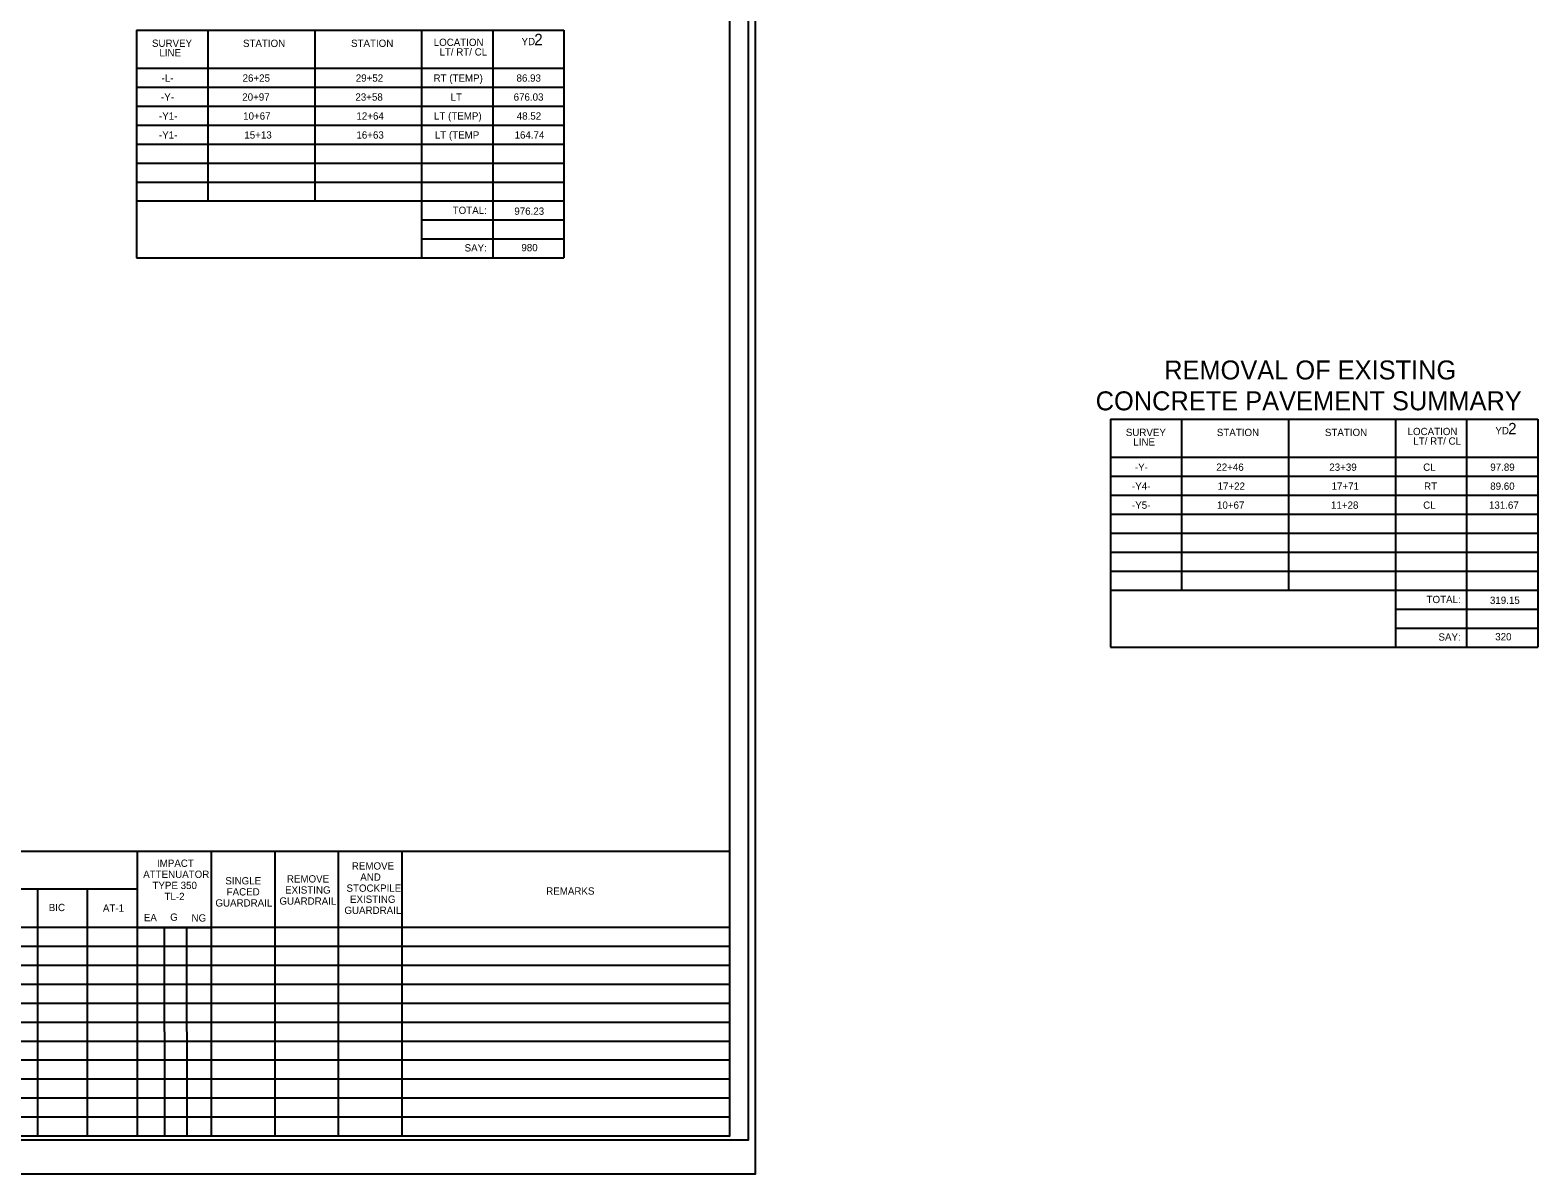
# Model space of a CAD drawing. Extents: x 1729625 to 1732014, y 538843 to 541329.
# Drawn here: x 1731022 to 1732014, y 539915 to 540668 of the extents above; entities that cross this region are included whole.
import ezdxf

# ---------------------------------------------------------------- set-up
doc = ezdxf.new("R2010")
doc.units = 0
for name, color, linetype in [('Prop EOT', 7, 'Continuous'), ('Prop Horizontal Alignment', 7, 'Continuous'), ('Sheet Cutting Line CELL', 7, 'Continuous'), ('Sheet Plot Border Inside CELL', 7, 'Continuous'), ('Sheet Plot Border Outside CELL', 7, 'Continuous'), ('Sheet Summary CELL', 7, 'Continuous')]:
    doc.layers.add(name, color=color, linetype=linetype)

msp = doc.modelspace()

# ---------------------------------------------------------------- linework, layer by layer
at = {"layer": 'Prop EOT'}
for p, q in [((1731092.06, 540668.17), (1731373.41, 540668.17)), ((1731092.06, 540668.17), (1731092.06, 540518.17)), ((1731138.96, 540668.17), (1731138.96, 540555.67)), ((1731209.31, 540668.17), (1731209.31, 540555.67)), ((1731279.61, 540668.17), (1731279.61, 540518.17)), ((1731326.51, 540668.17), (1731326.51, 540518.17)), ((1731373.41, 540668.17), (1731373.41, 540518.17)), ((1731092.06, 540643.17), (1731373.41, 540643.17)), ((1731092.06, 540630.67), (1731373.41, 540630.67)), ((1731092.06, 540618.17), (1731373.41, 540618.17)), ((1731092.06, 540605.67), (1731373.41, 540605.67)), ((1731092.06, 540593.17), (1731373.41, 540593.17)), ((1731092.06, 540580.67), (1731373.41, 540580.67)), ((1731092.06, 540568.17), (1731373.41, 540568.17)), ((1731092.06, 540555.67), (1731373.41, 540555.67)), ((1731279.61, 540543.17), (1731373.41, 540543.17)), ((1731279.61, 540530.67), (1731373.41, 540530.67)), ((1731092.06, 540518.17), (1731373.41, 540518.17)), ((1731733.08, 540411.88), (1732014.43, 540411.88)), ((1731733.08, 540411.88), (1731733.08, 540261.88)), ((1731779.98, 540411.88), (1731779.98, 540299.38)), ((1731850.33, 540411.88), (1731850.33, 540299.38)), ((1731920.63, 540411.88), (1731920.63, 540261.88)), ((1731967.53, 540411.88), (1731967.53, 540261.88)), ((1732014.43, 540411.88), (1732014.43, 540261.88)), ((1731733.08, 540386.88), (1732014.43, 540386.88)), ((1731733.08, 540374.38), (1732014.43, 540374.38)), ((1731733.08, 540361.88), (1732014.43, 540361.88)), ((1731733.08, 540349.38), (1732014.43, 540349.38)), ((1731733.08, 540336.88), (1732014.43, 540336.88)), ((1731733.08, 540324.38), (1732014.43, 540324.38)), ((1731733.08, 540311.88), (1732014.43, 540311.88)), ((1731733.08, 540299.38), (1732014.43, 540299.38)), ((1731920.63, 540286.88), (1732014.43, 540286.88)), ((1731920.63, 540274.38), (1732014.43, 540274.38)), ((1731733.08, 540261.88), (1732014.43, 540261.88)), ((1729982.47, 540127.41), (1731482.47, 540127.41)), ((1731092.42, 540127.41), (1731092.42, 539939.91)), ((1731141.27, 540127.41), (1731141.27, 539939.91)), ((1731183.07, 540127.41), (1731183.07, 539939.91)), ((1731224.87, 540127.41), (1731224.87, 539939.91)), ((1731266.72, 540127.41), (1731266.72, 539939.91)), ((1731092.42, 540102.41), (1730615.27, 540102.41)), ((1731026.82, 540102.41), (1731026.82, 539939.91)), ((1731059.62, 540102.41), (1731059.62, 539939.91)), ((1729982.47, 540077.41), (1731482.47, 540077.41)), ((1731092.42, 540077.16), (1731141.02, 540077.16)), ((1731110.28, 540077.16), (1731110.36, 539939.91)), ((1731125.02, 540077.16), (1731125.1, 539939.91)), ((1729982.47, 540064.91), (1731482.47, 540064.91)), ((1729982.47, 540052.41), (1731482.47, 540052.41)), ((1729982.47, 540039.91), (1731482.47, 540039.91)), ((1729982.47, 540027.41), (1731482.47, 540027.41)), ((1729982.47, 540014.91), (1731482.47, 540014.91)), ((1729982.47, 540002.41), (1731482.47, 540002.41)), ((1729982.47, 540002.41), (1731482.47, 540002.41)), ((1729982.47, 539989.91), (1731482.47, 539989.91)), ((1729982.47, 539977.41), (1731482.47, 539977.41)), ((1729982.47, 539964.91), (1731482.47, 539964.91)), ((1729982.47, 539952.41), (1731482.47, 539952.41))]:
    msp.add_line(p, q, dxfattribs=at)
at = {"layer": 'Prop Horizontal Alignment'}
for p, q in [((1731233.31, 540668.12), (1731233.31, 540668.12)), ((1731239.56, 540668.02), (1731239.56, 540668.02)), ((1731254.21, 540668.12), (1731254.21, 540668.12)), ((1731874.33, 540411.83), (1731874.33, 540411.83)), ((1731880.58, 540411.73), (1731880.58, 540411.73)), ((1731889.63, 540411.93), (1731889.63, 540411.93)), ((1731895.23, 540411.83), (1731895.23, 540411.83))]:
    msp.add_line(p, q, dxfattribs=at)
at = {"layer": 'Sheet Cutting Line CELL'}
msp.add_line((1729815.47, 539914.91), (1731499.47, 539914.91), dxfattribs=at)
at = {"layer": 'Sheet Plot Border Inside CELL'}
msp.add_lwpolyline([(1731494.97, 540992.46), (1729828.47, 540992.46), (1729828.47, 539937.36), (1731494.97, 539937.36)], close=True, dxfattribs=at)
at = {"layer": 'Sheet Plot Border Outside CELL'}
msp.add_lwpolyline([(1731499.47, 541014.91), (1729815.47, 541014.91), (1729815.47, 539914.91), (1731499.47, 539914.91)], close=True, dxfattribs=at)
at = {"layer": 'Sheet Summary CELL'}
msp.add_lwpolyline([(1731482.47, 540989.91), (1729982.47, 540989.91), (1729982.47, 539939.91), (1731482.47, 539939.91)], close=True, dxfattribs=at)

# ---------------------------------------------------------------- texts
at = {"layer": 'Prop EOT'}
for s, height, p in [('YD', 4.8, (1731345.47, 540658.29)), ('2', 7.5, (1731353.84, 540658.29)), ('2', 7.5, (1731994.85, 540402)), ('YD', 4.8, (1731986.48, 540402))]:
    msp.add_text(s, height=height, dxfattribs=at).set_placement(p)
at = {"layer": 'Prop Horizontal Alignment'}
for s, p in [('SURVEY', (1731102.21, 540657.18)), ('STATION', (1731162.11, 540657.13)), ('STATION', (1731233.25, 540657.15)), ('LOCATION', (1731287.66, 540657.77)), ('LINE', (1731107.11, 540650.88)), ('LT/ RT/ CL', (1731291.45, 540651.47)), ('-L-', (1731108.55, 540634.25)), ('26+25', (1731161.86, 540634.25)), ('29+52', (1731236.37, 540634.25)), ('RT (TEMP)', (1731287.56, 540634.25)), ('86.93', (1731342.17, 540634.25)), ('-Y-', (1731108.16, 540621.75)), ('20+97', (1731161.65, 540621.75)), ('23+58', (1731236.12, 540621.75)), ('LT', (1731298.81, 540621.75)), ('676.03', (1731340.27, 540621.75)), ('-Y1-', (1731106.84, 540609.25)), ('10+67', (1731162.23, 540609.25)), ('12+64', (1731236.82, 540609.25)), ('LT (TEMP)', (1731287.85, 540609.25)), ('48.52', (1731342.33, 540609.25)), ('-Y1-', (1731106.84, 540596.75)), ('15+13', (1731163.02, 540596.75)), ('16+63', (1731236.79, 540596.75)), ('LT (TEMP', (1731288.41, 540596.75)), ('164.74', (1731340.88, 540596.75)), ('TOTAL:', (1731300.16, 540547.12)), ('976.23', (1731340.73, 540546.58)), ('SAY:', (1731308, 540522.41)), ('980', (1731345.37, 540522.57)), ('SURVEY', (1731743.22, 540400.89)), ('LINE', (1731748.13, 540394.59)), ('STATION', (1731803.13, 540400.84)), ('STATION', (1731874.27, 540400.86)), ('LOCATION', (1731928.68, 540401.48)), ('LT/ RT/ CL', (1731932.47, 540395.18)), ('-Y-', (1731749.18, 540377.96)), ('22+46', (1731802.79, 540377.96)), ('23+39', (1731877.17, 540377.96)), ('CL', (1731938.95, 540377.96)), ('97.89', (1731983.12, 540377.96)), ('-Y4-', (1731747.28, 540365.46)), ('17+22', (1731803.61, 540365.46)), ('17+71', (1731878.65, 540365.46)), ('RT', (1731939.54, 540365.46)), ('89.60', (1731983.08, 540365.46)), ('-Y5-', (1731747.28, 540352.96)), ('10+67', (1731803.24, 540352.96)), ('11+28', (1731878.28, 540352.96)), ('CL', (1731938.95, 540352.96)), ('131.67', (1731982.23, 540352.96)), ('TOTAL:', (1731941.18, 540290.83)), ('319.15', (1731982.89, 540290.29)), ('SAY:', (1731949.02, 540266.12)), ('320', (1731986.38, 540266.29)), ('IMPACT', (1731105.51, 540117.11)), ('ATTENUATOR', (1731096.45, 540109.81)), ('REMOVE', (1731191.02, 540106.81)), ('REMOVE', (1731233.77, 540115.31)), ('AND', (1731239.32, 540108.01)), ('TYPE 350', (1731102.55, 540102.51)), ('SINGLE', (1731150.52, 540105.56)), ('FACED', (1731151.37, 540098.26)), ('EXISTING', (1731189.82, 540099.51)), ('STOCKPILE', (1731230.27, 540100.71)), ('REMARKS', (1731361.72, 540098.81)), ('BIC', (1731034.27, 540087.96)), ('AT-1', (1731069.92, 540087.56)), ('TL-2', (1731110.44, 540095.21)), ('GUARDRAIL', (1731143.97, 540090.96)), ('GUARDRAIL', (1731186.12, 540092.21)), ('EXISTING', (1731232.57, 540093.41)), ('EA', (1731096.87, 540081.26)), ('G', (1731114.22, 540081.61)), ('NG', (1731128.27, 540081.06)), ('GUARDRAIL', (1731228.87, 540086.11))]:
    msp.add_text(s, height=4.8, dxfattribs=at).set_placement(p)
for s, p in [('REMOVAL OF EXISTING ', (1731768.45, 540438.1)), ('CONCRETE PAVEMENT SUMMARY', (1731723.38, 540417.78))]:
    msp.add_text(s, height=12.5001, rotation=0.01193, dxfattribs=at).set_placement(p)

doc.saveas('drawing.dxf')
